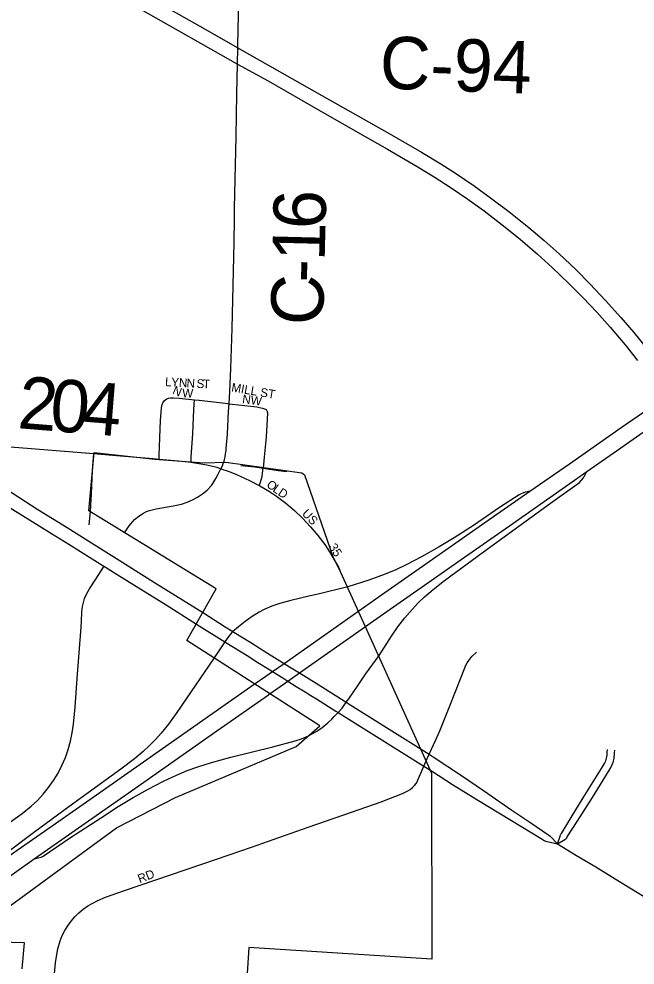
# Model space of a CAD drawing. Extents: x -49 to -8.2, y 9.4 to 23.5.
# Drawn here: x -9.083 to -8.749, y 11.132 to 11.645 of the extents above; entities that cross this region are included whole.
import ezdxf

# ---------------------------------------------------------------- set-up
doc = ezdxf.new("R2010")
doc.units = 0
for name, color, linetype in [('GM_X_City_Street', 7, 'Continuous'), ('GM_X_City_Street_Text', 7, 'Continuous'), ('GM_X_Corporation', 7, 'Continuous'), ('GM_X_County_Road', 7, 'Continuous'), ('GM_X_County_Road_Text', 7, 'Continuous'), ('GM_X_Interchange_Ramps', 7, 'Continuous'), ('GM_X_Interstate_Route', 7, 'Continuous'), ('GM_X_State_Route', 7, 'Continuous'), ('GM_X_Township_Road', 7, 'Continuous'), ('GM_X_Township_Subdivision', 7, 'Continuous'), ('GM_X_Township_Subdivision_Text', 7, 'Continuous'), ('GM_X_US_Route', 7, 'Continuous')]:
    doc.layers.add(name, color=color, linetype=linetype)

msp = doc.modelspace()

# ---------------------------------------------------------------- linework, layer by layer
at = {"layer": 'GM_X_City_Street'}
for points in [[(-9.02536, 11.36607), (-9.02285, 11.36988), (-9.02097, 11.37218), (-9.01993, 11.37323), (-9.01763, 11.37513), (-9.01516, 11.37678), (-9.01387, 11.37744), (-9.01252, 11.37797), (-9.0111, 11.37841), (-9.00815, 11.3791), (-8.99906, 11.38076), (-8.99446, 11.3817), (-8.99143, 11.38268), (-8.98852, 11.38395), (-8.98573, 11.38546), (-8.98309, 11.38724), (-8.98066, 11.38928), (-8.97825, 11.39181), (-8.97742, 11.39291), (-8.97584, 11.39552), (-8.97456, 11.39796), (-8.97309, 11.40088)], [(-8.97309, 11.40088), (-8.96856, 11.39928), (-8.96458, 11.39772), (-8.95755, 11.39449), (-8.95237, 11.39179)], [(-8.96231, 11.40266), (-8.95471, 11.40186), (-8.95016, 11.40116)], [(-8.95237, 11.39179), (-8.95191, 11.39308), (-8.95126, 11.39491), (-8.95078, 11.39669), (-8.95056, 11.39838), (-8.95016, 11.40116)], [(-8.95016, 11.40116), (-8.94216, 11.39994), (-8.93743, 11.39938)], [(-8.95237, 11.39179), (-8.95206, 11.39163), (-8.94675, 11.38846), (-8.9429, 11.38588), (-8.93796, 11.38215), (-8.93324, 11.37816), (-8.92875, 11.3739), (-8.92451, 11.36939), (-8.92052, 11.36466), (-8.91681, 11.35972), (-8.91422, 11.35587), (-8.91234, 11.35277)], [(-9.06413, 11.11898), (-9.06281, 11.13285), (-9.06214, 11.13742), (-9.06148, 11.14042), (-9.06024, 11.14487), (-9.05917, 11.14772), (-9.05774, 11.15041), (-9.05608, 11.153), (-9.05426, 11.15547), (-9.05228, 11.15781), (-9.05013, 11.15999), (-9.04781, 11.16198), (-9.0453, 11.16373), (-9.04266, 11.16529), (-9.03992, 11.16669), (-9.03568, 11.16851), (-9.02547, 11.17214), (-8.97555, 11.18914), (-8.95649, 11.19568), (-8.92575, 11.20645), (-8.90229, 11.21452), (-8.88622, 11.22024), (-8.8746, 11.22472), (-8.87178, 11.22612), (-8.87044, 11.22698), (-8.86919, 11.22799), (-8.86809, 11.22915), (-8.86711, 11.23042), (-8.86304, 11.23963)]]:
    msp.add_lwpolyline(points, dxfattribs=at)
at = {"layer": 'GM_X_Corporation'}
msp.add_lwpolyline([(-9.08084, 11.12967), (-9.07972, 11.14383), (-9.1138, 11.14473), (-9.02969, 11.20618), (-8.99772, 11.22254), (-8.93232, 11.25023), (-8.91945, 11.2614), (-8.99158, 11.30761), (-8.97566, 11.3357), (-9.04472, 11.378), (-9.04192, 11.40966), (-9.00901, 11.40608), (-8.98953, 11.40459), (-8.98215, 11.40411), (-8.9704, 11.4044), (-8.92924, 11.39868), (-8.9278, 11.39745), (-8.91242, 11.35327), (-8.90818, 11.3448), (-8.89485, 11.31534), (-8.85883, 11.23572), (-8.8587, 11.13482), (-8.95792, 11.14127), (-8.97172, 10.92894)], dxfattribs=at)
at = {"layer": 'GM_X_County_Road'}
for points in [[(-8.96575, 11.53644), (-8.9657, 11.54214), (-8.96491, 11.58093), (-8.9644, 11.60422), (-8.96406, 11.62031), (-8.9639, 11.62902), (-8.96388, 11.63061), (-8.96345, 11.65544), (-8.96337, 11.65929)], [(-8.96872, 11.43611), (-8.96831, 11.44279), (-8.96772, 11.4552), (-8.96704, 11.47694), (-8.96587, 11.52351), (-8.96575, 11.53644)], [(-8.97309, 11.40088), (-8.97232, 11.40246), (-8.97187, 11.4036), (-8.97142, 11.40488), (-8.97116, 11.40589), (-8.97084, 11.40726), (-8.97055, 11.40885), (-8.97031, 11.41065), (-8.97019, 11.41183), (-8.96963, 11.41958), (-8.96897, 11.43196), (-8.96872, 11.43611)], [(-9.12054, 11.41733), (-9.10978, 11.41523), (-9.10359, 11.41431), (-9.09425, 11.41331), (-9.04195, 11.40908)], [(-9.04389, 11.37778), (-9.0433, 11.38718), (-9.04273, 11.39981), (-9.04236, 11.40453), (-9.04195, 11.40908)], [(-9.04195, 11.40908), (-9.02973, 11.40808), (-9.00982, 11.40636), (-9.00664, 11.40608)], [(-9.00664, 11.40608), (-8.99603, 11.40516), (-8.98934, 11.40436)], [(-8.98934, 11.40436), (-8.9884, 11.40425), (-8.98081, 11.40298), (-8.97678, 11.40214), (-8.97539, 11.4017), (-8.97406, 11.40123), (-8.97309, 11.40088)], [(-9.0445, 11.37051), (-9.0442, 11.37381), (-9.04389, 11.37778)], [(-8.91234, 11.35277), (-8.90931, 11.34739), (-8.90859, 11.34603)], [(-8.8602, 11.24598), (-8.85665, 11.25382), (-8.85448, 11.25872), (-8.8493, 11.27141), (-8.84251, 11.28864), (-8.84022, 11.2943), (-8.83953, 11.29564), (-8.83875, 11.2969), (-8.83784, 11.29807), (-8.83681, 11.29917), (-8.83459, 11.30133)], [(-8.79065, 11.19739), (-8.78918, 11.20168), (-8.78894, 11.20227), (-8.78874, 11.20268), (-8.78848, 11.20312), (-8.78315, 11.21178), (-8.77661, 11.22237), (-8.76664, 11.2382), (-8.76509, 11.24094), (-8.76443, 11.24238), (-8.76393, 11.24392), (-8.76369, 11.24553), (-8.7636, 11.24709), (-8.76342, 11.24857)], [(-8.79065, 11.19739), (-8.78659, 11.19974), (-8.78608, 11.20017), (-8.78556, 11.20074), (-8.78529, 11.20116), (-8.77987, 11.20955), (-8.77578, 11.21603), (-8.77168, 11.22252), (-8.76439, 11.23427), (-8.76205, 11.23819), (-8.76073, 11.24088), (-8.76024, 11.24227), (-8.75991, 11.24371), (-8.75964, 11.24671), (-8.75956, 11.24825)], [(-8.86304, 11.23963), (-8.86127, 11.24364), (-8.8602, 11.24598)]]:
    msp.add_lwpolyline(points, dxfattribs=at)
at = {"layer": 'GM_X_Interchange_Ramps'}
for points in [[(-8.90952, 11.2687), (-8.90736, 11.27106), (-8.90516, 11.27419), (-8.90378, 11.27615), (-8.90095, 11.28011), (-8.89903, 11.28288), (-8.89464, 11.2895), (-8.88734, 11.29961), (-8.88064, 11.31001), (-8.87711, 11.31511), (-8.87334, 11.32004), (-8.86931, 11.32477), (-8.8661, 11.32814), (-8.86273, 11.33135), (-8.85801, 11.33537), (-8.8519, 11.34015), (-8.83064, 11.35578), (-8.79432, 11.38212), (-8.77871, 11.39345), (-8.77759, 11.39458), (-8.77654, 11.39586), (-8.77586, 11.39698), (-8.77459, 11.39931)], [(-8.80556, 11.38861), (-8.80701, 11.38833), (-8.80818, 11.38809), (-8.80937, 11.38766), (-8.81038, 11.38719), (-8.81133, 11.38665), (-8.82195, 11.37981), (-8.83619, 11.37011), (-8.84669, 11.36329), (-8.85474, 11.35844), (-8.8643, 11.35307), (-8.87263, 11.34872), (-8.87829, 11.34605), (-8.88407, 11.34365), (-8.89291, 11.34046), (-8.90424, 11.33682), (-8.9203, 11.33289), (-8.92478, 11.33197), (-8.9352, 11.32939), (-8.9411, 11.32775), (-8.94543, 11.32628), (-8.94964, 11.32451), (-8.95235, 11.32312), (-8.95624, 11.32074), (-8.95995, 11.31806), (-8.96354, 11.3152), (-8.96662, 11.31253), (-8.96717, 11.312), (-8.9688, 11.31014), (-8.97095, 11.30704)], [(-8.97095, 11.30704), (-8.97324, 11.30367), (-8.97684, 11.29838), (-8.99705, 11.26861), (-9.0016, 11.26233), (-9.00549, 11.25749), (-9.00859, 11.25401), (-9.01185, 11.25069), (-9.01526, 11.24753), (-9.02004, 11.24356), (-9.02745, 11.23793), (-9.05554, 11.21746), (-9.074, 11.20388), (-9.10274, 11.1825), (-9.11405, 11.17443), (-9.11502, 11.1735), (-9.11566, 11.17262), (-9.1164, 11.17094)], [(-9.07438, 11.18928), (-9.07216, 11.1898), (-9.07067, 11.19026), (-9.06945, 11.19075), (-9.06202, 11.19581), (-9.05462, 11.20084), (-9.03794, 11.21174), (-9.02878, 11.21768), (-9.02076, 11.22249), (-9.0126, 11.22706), (-9.0043, 11.23138), (-8.99725, 11.23472), (-8.9915, 11.23712), (-8.98564, 11.23924), (-8.97819, 11.24154), (-8.96765, 11.24438), (-8.94494, 11.24996), (-8.93291, 11.25325), (-8.92936, 11.25444), (-8.92558, 11.25593), (-8.92111, 11.25861), (-8.91822, 11.2606), (-8.91514, 11.26309), (-8.91305, 11.26498), (-8.91169, 11.26645), (-8.90952, 11.2687)]]:
    msp.add_lwpolyline(points, dxfattribs=at)
at = {"layer": 'GM_X_Interstate_Route'}
for points in [[(-8.89462, 11.31531), (-8.89215, 11.31705), (-8.84274, 11.35156), (-8.81476, 11.37118), (-8.77459, 11.39931), (-8.75624, 11.4122), (-8.7308, 11.43003), (-8.72762, 11.43231), (-8.72124, 11.43681), (-8.70316, 11.44959), (-8.6807, 11.46518), (-8.6585, 11.4806), (-8.61579, 11.5106), (-8.58278, 11.53359), (-8.53333, 11.56834), (-8.50918, 11.58531), (-8.49099, 11.59778), (-8.47051, 11.61131), (-8.4532, 11.62231), (-8.43309, 11.63468), (-8.4141, 11.6459)], [(-9.18387, 11.1234), (-9.12487, 11.16495), (-9.1164, 11.17094), (-9.10327, 11.18017), (-9.08543, 11.19268), (-9.06281, 11.2085), (-9.04246, 11.22278), (-8.98115, 11.26573), (-8.95507, 11.28396), (-8.94881, 11.28834), (-8.94512, 11.29092), (-8.93887, 11.2953), (-8.91675, 11.3108), (-8.89835, 11.3237), (-8.88597, 11.33238), (-8.85473, 11.35438), (-8.8295, 11.37197), (-8.80556, 11.38861), (-8.78413, 11.40359), (-8.75611, 11.42316), (-8.7348, 11.43791)], [(-8.94282, 11.28148), (-8.93679, 11.28572), (-8.93052, 11.29011), (-8.91708, 11.29958), (-8.89462, 11.31531)], [(-9.39804, 10.96244), (-9.35829, 10.99048), (-9.35286, 10.99411), (-9.32677, 11.01264), (-9.2944, 11.03518), (-9.24761, 11.06801), (-9.24485, 11.06995), (-9.2298, 11.0805), (-9.19699, 11.10351), (-9.15802, 11.13074), (-9.09589, 11.17417), (-9.07438, 11.18928), (-9.0486, 11.20738), (-9.02162, 11.22626), (-8.97533, 11.25872), (-8.94733, 11.27831), (-8.94691, 11.27861)], [(-8.94691, 11.27861), (-8.94282, 11.28148)]]:
    msp.add_lwpolyline(points, dxfattribs=at)
at = {"layer": 'GM_X_State_Route'}
for points in [[(-9.15281, 11.42149), (-9.15277, 11.42146), (-9.13472, 11.40932), (-9.09258, 11.38288), (-9.06496, 11.36571)], [(-9.09326, 11.39211), (-9.07233, 11.37872), (-9.05645, 11.36898), (-9.0433, 11.36075), (-9.0327, 11.35406), (-9.03181, 11.35351), (-9.00915, 11.33921), (-8.98265, 11.32265), (-8.97076, 11.31519), (-8.96662, 11.31253), (-8.96609, 11.3122), (-8.95696, 11.30654), (-8.94779, 11.30081), (-8.93887, 11.2953), (-8.93594, 11.29348), (-8.93052, 11.29011), (-8.92149, 11.2845), (-8.90632, 11.27493), (-8.90516, 11.27419), (-8.90265, 11.27267), (-8.87036, 11.25244), (-8.8602, 11.24598), (-8.85807, 11.24458), (-8.84261, 11.2345), (-8.83073, 11.2263), (-8.8154, 11.21571), (-8.80505, 11.2088), (-8.79585, 11.20258), (-8.79526, 11.20214), (-8.79463, 11.20152), (-8.79065, 11.19739)], [(-9.06496, 11.36571), (-9.05561, 11.3599), (-9.03654, 11.34793), (-9.0357, 11.3474), (-9.02796, 11.34254), (-9.00279, 11.32708), (-8.98627, 11.31659)], [(-8.98627, 11.31659), (-8.97095, 11.30704), (-8.97039, 11.30669), (-8.9589, 11.2995), (-8.95302, 11.29576), (-8.94797, 11.29268), (-8.94512, 11.29092), (-8.9396, 11.28747)], [(-8.9396, 11.28747), (-8.93679, 11.28572), (-8.93233, 11.28284), (-8.92743, 11.27983), (-8.92432, 11.27794), (-8.92134, 11.27603), (-8.91075, 11.26946), (-8.90952, 11.2687), (-8.87378, 11.24631), (-8.86304, 11.23963)], [(-8.86304, 11.23963), (-8.85892, 11.23695), (-8.84761, 11.22957), (-8.83427, 11.22139), (-8.81552, 11.21005), (-8.79947, 11.20031), (-8.79786, 11.19933), (-8.79705, 11.19892), (-8.79626, 11.19863), (-8.79065, 11.19739)], [(-8.79065, 11.19739), (-8.78036, 11.19106), (-8.76986, 11.18496), (-8.76072, 11.17932)], [(-8.76072, 11.17932), (-8.75935, 11.17847), (-8.74164, 11.16754), (-8.72783, 11.15941), (-8.71019, 11.14917), (-8.69713, 11.14165)]]:
    msp.add_lwpolyline(points, dxfattribs=at)
at = {"layer": 'GM_X_Township_Road'}
for points in [[(-9.04879, 11.31806), (-9.04848, 11.32327), (-9.04818, 11.32617), (-9.0479, 11.32761), (-9.04752, 11.32904), (-9.04704, 11.33043), (-9.04582, 11.33313), (-9.04435, 11.33576), (-9.04104, 11.34091), (-9.03686, 11.34742), (-9.03654, 11.34793)], [(-9.08842, 11.20839), (-9.08092, 11.21393), (-9.07608, 11.21783), (-9.07264, 11.22097), (-9.06946, 11.22437), (-9.06654, 11.228), (-9.06386, 11.23182), (-9.06146, 11.23581), (-9.05934, 11.23997), (-9.05749, 11.24424), (-9.05595, 11.24864), (-9.05468, 11.25312), (-9.05371, 11.25768), (-9.05307, 11.2623), (-9.0521, 11.27157), (-9.0511, 11.28707), (-9.04897, 11.31496), (-9.04879, 11.31806)]]:
    msp.add_lwpolyline(points, dxfattribs=at)
at = {"layer": 'GM_X_Township_Subdivision'}
for points in [[(-9.00664, 11.40608), (-9.00657, 11.40819), (-9.00627, 11.41768), (-9.00586, 11.42722), (-9.00539, 11.43355), (-9.00512, 11.4351), (-9.00464, 11.43658), (-9.00376, 11.43787), (-9.00248, 11.43878)], [(-9.00248, 11.43878), (-9.00151, 11.43913), (-9.00048, 11.43929), (-8.99891, 11.43932), (-8.99578, 11.43912), (-8.98743, 11.43822)], [(-8.98934, 11.40436), (-8.98917, 11.40738), (-8.98891, 11.41213), (-8.98837, 11.42004), (-8.98786, 11.43273), (-8.98761, 11.43589), (-8.98743, 11.43822)], [(-8.98743, 11.43822), (-8.98485, 11.43794), (-8.97082, 11.43634), (-8.96872, 11.43611)], [(-8.96872, 11.43611), (-8.95522, 11.43461), (-8.9537, 11.43435), (-8.95214, 11.43404), (-8.95064, 11.43363), (-8.94953, 11.43332), (-8.94896, 11.43307), (-8.94865, 11.4329), (-8.94839, 11.43266), (-8.94819, 11.43235), (-8.94808, 11.4321), (-8.94795, 11.43162), (-8.9479, 11.43122), (-8.94863, 11.41805), (-8.94962, 11.40712), (-8.95016, 11.40116)]]:
    msp.add_lwpolyline(points, dxfattribs=at)
at = {"layer": 'GM_X_US_Route'}
for points in [[(-9.05439, 11.6715), (-9.00713, 11.64462), (-8.97333, 11.62549), (-8.96406, 11.62031), (-8.94755, 11.61112), (-8.91926, 11.59488), (-8.89362, 11.58026), (-8.88284, 11.57409), (-8.8667, 11.56475), (-8.85739, 11.55911), (-8.84823, 11.55322), (-8.83925, 11.54708), (-8.83044, 11.54068), (-8.82058, 11.5331), (-8.81091, 11.52528), (-8.80146, 11.5172), (-8.79339, 11.5099), (-8.78438, 11.50132), (-8.7767, 11.49361), (-8.76922, 11.4857), (-8.76196, 11.47759), (-8.75393, 11.46809), (-8.74713, 11.45959)], [(-9.02785, 11.66535), (-8.98458, 11.64091), (-8.9639, 11.62902), (-8.96304, 11.62852), (-8.91843, 11.60327), (-8.88194, 11.58259), (-8.86442, 11.57258), (-8.85379, 11.56616), (-8.84596, 11.56114), (-8.83569, 11.55417), (-8.82687, 11.54782), (-8.81698, 11.54033), (-8.80607, 11.53162), (-8.79778, 11.52461), (-8.78969, 11.51736), (-8.7807, 11.50881), (-8.77302, 11.50113), (-8.76447, 11.49213), (-8.75616, 11.48292), (-8.74912, 11.47465), (-8.74232, 11.46618)]]:
    msp.add_lwpolyline(points, dxfattribs=at)

# ---------------------------------------------------------------- texts
at = {"layer": 'GM_X_City_Street_Text'}
for s, height, rotation, p in [('O', 0.00473, 323.7814, (-8.94879, 11.39135)), ('L', 0.00473, 324.2077, (-8.9454, 11.38887)), ('D', 0.00473, 325.8628, (-8.94258, 11.38683)), ('US', 0.004735, 313.5283, (-8.9295, 11.37624)), ('35', 0.004735, 301.6037, (-8.9148, 11.35858)), ('RD', 0.004735, 21.2634, (-9.01714, 11.17603))]:
    msp.add_text(s, height=height, rotation=rotation, dxfattribs=at).set_placement(p)
at = {"layer": 'GM_X_County_Road_Text'}
for s, height, rotation, p in [('C-94', 0.028409, 357.9422, (-8.88735, 11.60714)), ('6', 0.02841, 88.6665, (-8.91644, 11.5306)), ('1', 0.02841, 88.5845, (-8.91687, 11.5132)), ('-', 0.02841, 88.4943, (-8.91717, 11.50159)), ('C', 0.02841, 88.4422, (-8.9178, 11.47841)), ('2', 0.02841, 355.3396, (-9.08382, 11.42288)), ('0', 0.02841, 355.377, (-9.06649, 11.42146)), ('4', 0.02841, 355.3781, (-9.04919, 11.42007))]:
    msp.add_text(s, height=height, rotation=rotation, dxfattribs=at).set_placement(p)
at = {"layer": 'GM_X_Township_Subdivision_Text'}
for s, height, rotation, p in [('L', 0.00473, 356.7747, (-9.00351, 11.44569)), ('Y', 0.00473, 356.784, (-9.00018, 11.4455)), ('N', 0.00473, 356.7632, (-8.99602, 11.44527)), ('N', 0.00473, 356.784, (-8.99186, 11.44504)), ('S', 0.00473, 356.7747, (-8.98645, 11.44473)), ('T', 0.00473, 358.3479, (-8.98298, 11.44454)), ('MILL ST', 0.004735, 350.3344, (-8.96771, 11.44278)), ('N', 0.00473, 337.407, (-8.99977, 11.4416)), ('W', 0.00473, 357.7986, (-8.99417, 11.43961)), ('NW', 0.004735, 352.5641, (-8.96176, 11.43643))]:
    msp.add_text(s, height=height, rotation=rotation, dxfattribs=at).set_placement(p)

doc.saveas('drawing.dxf')
